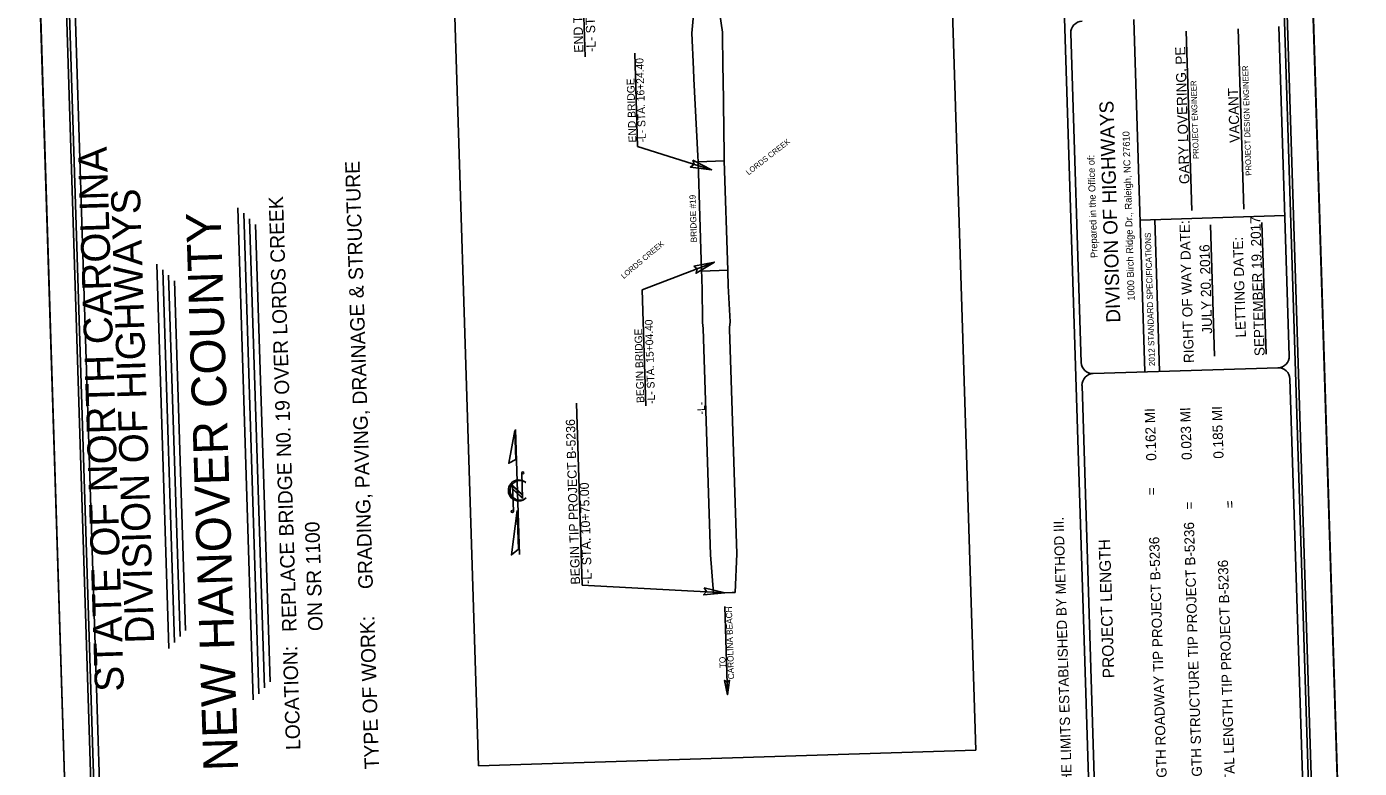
# Model space of a CAD drawing. Extents: x 2308163 to 2335412, y -96774 to 125428.
# Drawn here: x 2325774 to 2327503, y 123508 to 124471 of the extents above; entities that cross this region are included whole.
import ezdxf

# ---------------------------------------------------------------- set-up
doc = ezdxf.new("R2010")
doc.units = 0
for name, color, linetype in [('Prop Horizontal Alignment', 7, 'Continuous'), ('Prop Horizontal Alignment Station Label', 7, 'Continuous'), ('Prop Shade Light', 7, 'Continuous'), ('Prop Shade Medium', 7, 'Continuous'), ('Prop Terminator CELL', 7, 'Continuous'), ('Sheet Cutting Line CELL', 7, 'Continuous'), ('Sheet Data Text CELL', 7, 'Continuous'), ('Sheet North Arrow CELL', 7, 'Continuous'), ('Sheet Plan Layout CELL', 7, 'Continuous'), ('Sheet Plot Border Inside CELL', 7, 'Continuous'), ('Sheet Plot Border Outside CELL', 7, 'Continuous'), ('Sheet Title CELL', 7, 'Continuous'), ('Sheet Title Data Points CELL', 7, 'Continuous'), ('Typical Terminator CELL', 7, 'Continuous')]:
    doc.layers.add(name, color=color, linetype=linetype)

# ---------------------------------------------------------------- blocks, each defined once
blk = doc.blocks.new('NORTH ARROW')
at = {"layer": 'Sheet North Arrow CELL'}
for p, q in [((0, -3.25), (0, 3.25)), ((0.245, 0.988), (0.245, -0.346)), ((0.245, -0.138), (-0.252, 0.359)), ((-0.252, 0.359), (-0.252, -0.997)), ((0.245, -0.187), (-0.252, 0.31)), ((-0.252, 0.31), (-0.252, 0.188)), ((0.245, -0.309), (-0.252, 0.188)), ((-0.252, 0.188), (0.245, -0.309)), ((0.245, -0.346), (-0.252, 0.151)), ((0.429, 0.491), (0.436, 0.486)), ((0.245, -0.309), (0.245, -0.187))]:
    blk.add_line(p, q, dxfattribs=at)
for points in [[(-0.045, 3.193), (-0.416, 1.505), (-0.045, 1.693)], [(-0.053, -0.96), (-0.421, -3.25), (-0.053, -2.96)]]:
    blk.add_lwpolyline(points, close=True, dxfattribs=at)
for centre in [(0.298, 0.987), (-0.305, -0.999)]:
    blk.add_circle(centre, 0.053, dxfattribs=at)
for centre, radius, start, end in [((0.069, 0.081), 0.546, 47.84002, 312.39406), ((0.122, 0.082), 0.512, 53.09504, 308.62871)]:
    blk.add_arc(centre, radius, start, end, dxfattribs=at)
blk = doc.blocks.new('TERMINATOR')
at = {"layer": 'Typical Terminator CELL'}
blk.add_lwpolyline([(-0.469, 0.081), (0, 0), (-0.471, -0.083), (-0.411, 0)], close=True, dxfattribs=at)

msp = doc.modelspace()

# ---------------------------------------------------------------- linework, layer by layer
at = {"layer": 'Prop Horizontal Alignment'}
for p, q in [((2326491.4, 124659.7), (2326498.6, 124431.4)), ((2326562.8, 124436.4), (2326566.6, 124315)), ((2326566.6, 124315), (2326662.4, 124284.9)), ((2326666.1, 124165), (2326572.5, 124128.9)), ((2326572.5, 124128.9), (2326577.2, 123978.7)), ((2326487.3, 123982.1), (2326494.8, 123745.6)), ((2326679.6, 123735.8), (2326494.8, 123745.6)), ((2326683.3, 123603.4), (2326679.7, 123718))]:
    msp.add_line(p, q, dxfattribs=at)
at = {"layer": 'Prop Shade Light'}
for p, q in [((2326677.6, 124404.2), (2326677.2, 124416.7)), ((2326639.6, 124403), (2326644.8, 124303.1)), ((2326678.8, 124304.2), (2326677.6, 124404.2)), ((2326677.6, 124404.2), (2326677.6, 124404.2)), ((2326644.8, 124303.1), (2326644.8, 124303.1)), ((2326644.8, 124303.1), (2326644.8, 124303.1)), ((2326644.8, 124303.1), (2326645, 124295.4)), ((2326645, 124295.4), (2326679, 124296.4)), ((2326679, 124296.4), (2326678.8, 124304.2)), ((2326683.5, 124154.5), (2326649.5, 124153.4)), ((2326649.5, 124153.4), (2326649.7, 124145.7)), ((2326649.7, 124145.7), (2326649.9, 124139.5)), ((2326649.9, 124139.5), (2326649.9, 124139.5)), ((2326683.7, 124146.8), (2326683.5, 124154.5)), ((2326683.9, 124140.5), (2326683.7, 124146.8)), ((2326651.8, 124079), (2326661.1, 123785.2)), ((2326685.9, 124077.8), (2326685.8, 124080.1)), ((2326695.1, 123786.3), (2326685.9, 124077.8)), ((2326661.1, 123785.2), (2326665.2, 123735.3)), ((2326693.3, 123736.2), (2326695.1, 123786.3)), ((2326665.2, 123735.3), (2326669.8, 123735.5)), ((2326669.8, 123735.5), (2326689.4, 123736.1)), ((2326689.4, 123736.1), (2326693.3, 123736.2))]:
    msp.add_line(p, q, dxfattribs=at)
for points in [[(2326633.5, 124659.8), (2326639, 124485.8), (2326636.8, 124462.2), (2326639.2, 124415.5), (2326639.6, 124403)], [(2326677.2, 124416.7), (2326676.7, 124463.4), (2326673, 124486.8), (2326667.5, 124660.9)], [(2326649.9, 124139.5), (2326650.1, 124133.2), (2326650.7, 124086.5), (2326651.8, 124079)], [(2326685.8, 124080.1), (2326686.5, 124087.6), (2326684.1, 124134.3), (2326683.9, 124140.5)]]:
    msp.add_lwpolyline(points, dxfattribs=at)
at = {"layer": 'Prop Shade Medium'}
msp.add_lwpolyline([(2326683.5, 124154.5), (2326679, 124296.4), (2326645, 124295.4), (2326649.5, 124153.4), (2326683.5, 124154.5)], dxfattribs=at)
at = {"layer": 'Prop Terminator CELL'}
for points in [[(2326638, 124297.4), (2326662.4, 124284.9), (2326635, 124288.5), (2326639.7, 124292)], [(2326639.3, 124159.6), (2326666.1, 124165), (2326642.5, 124150.7), (2326644, 124156.5)], [(2326653, 123742.4), (2326679.6, 123735.9), (2326652.2, 123733), (2326656, 123737.5)]]:
    msp.add_lwpolyline(points, close=True, dxfattribs=at)
at = {"layer": 'Sheet Cutting Line CELL'}
for p, q in [((2327502.8, 122587.5), (2327423.2, 125112.3)), ((2325853.6, 122535.6), (2325774, 125060.3))]:
    msp.add_line(p, q, dxfattribs=at)
at = {"layer": 'Sheet Plan Layout CELL'}
msp.add_lwpolyline([(2326360.1, 123511.4), (2326318.3, 124840), (2326963.2, 124860.3), (2327005.1, 123531.7)], close=True, dxfattribs=at)
at = {"layer": 'Sheet Plot Border Inside CELL'}
msp.add_lwpolyline([(2327468.5, 122606), (2327389.8, 125104.5), (2325807.9, 125054.6), (2325886.6, 122556.1)], close=True, dxfattribs=at)
at = {"layer": 'Sheet Plot Border Outside CELL'}
msp.add_lwpolyline([(2325774, 125060.3), (2325853.6, 122535.6), (2327502.8, 122587.5), (2327423.2, 125112.3)], close=True, dxfattribs=at)
at = {"layer": 'Sheet Title CELL'}
for p, q in [((2327169.5, 122925.2), (2327102.4, 125054.2)), ((2327210.2, 124479.8), (2327224.6, 124022.5)), ((2327353, 124233.8), (2327345.6, 124468)), ((2327142, 124034.9), (2327128.5, 124462.2)), ((2327285.5, 124232.2), (2327278.2, 124464.8)), ((2326068, 123597), (2326047.9, 124235.7)), ((2326075.2, 123604.7), (2326055.6, 124228.4)), ((2326082.5, 123612.4), (2326063.3, 124221.1)), ((2326089.8, 123620.2), (2326071.1, 124213.9)), ((2327218.3, 124219.7), (2327406.1, 124225.6)), ((2327237.5, 124220.3), (2327243.7, 124023.1)), ((2327309.5, 124213.6), (2327314.8, 124043)), ((2327376.3, 124216.3), (2327381.7, 124045.7)), ((2325958.4, 123663.5), (2325942.7, 124162.4)), ((2327239.2, 124163.5), (2327239.2, 124163.5)), ((2325965.7, 123671.3), (2325950.5, 124155.2)), ((2325973, 123679), (2325958.2, 124147.9)), ((2325980.2, 123686.7), (2325965.9, 124140.6)), ((2327312.2, 124128.3), (2327312.2, 124128.3)), ((2327157.5, 124020.4), (2327397.3, 124027.9)), ((2327160.9, 123435.2), (2327143, 124004.9))]:
    msp.add_line(p, q, dxfattribs=at)
for points in [[(2327456.9, 122851.7), (2327387, 125070.6)], [(2325812.8, 125021), (2325882.7, 122802.1)], [(2325820.5, 125013.8), (2325887.6, 122884.8)], [(2327411.9, 124043.4), (2327398.4, 124470.7)], [(2327430.8, 123443.7), (2327412.8, 124013.4)]]:
    msp.add_lwpolyline(points, dxfattribs=at)
for centre, start, end in [((2327143.5, 124462.7), 91.8048, 181.8048), ((2327396.8, 124042.9), 271.8048, 1.8048), ((2327156.9, 124035.4), 181.8048, 271.8048), ((2327157.9, 124005.4), 91.8048, 181.8048), ((2327397.7, 124012.9), 1.8048, 91.8048)]:
    msp.add_arc(centre, 15, start, end, dxfattribs=at)
at = {"layer": 'Sheet Title Data Points CELL'}
for p, q in [((2326113.9, 124018.4), (2326113.9, 124018.4)), ((2326035.5, 123917.9), (2326035.5, 123917.9))]:
    msp.add_line(p, q, dxfattribs=at)

# ---------------------------------------------------------------- block references
at = {"layer": 'Prop Horizontal Alignment', "xscale": 40, "yscale": 40.00000000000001, "rotation": -88.19520799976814}
msp.add_blockref('TERMINATOR', (2326683.3, 123603.4), dxfattribs=at)
at = {"layer": 'Sheet Plan Layout CELL', "xscale": 25.000000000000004, "yscale": 25, "rotation": 1.8047920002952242}
msp.add_blockref('NORTH ARROW', (2326410.9, 123866.6), dxfattribs=at)

# ---------------------------------------------------------------- texts
at = {"layer": 'Prop Horizontal Alignment'}
for s, height, rotation, p in [('END TIP PROJECT B-5236', 12, 91.8048, (2326496.4, 124437)), ('-L- STA. 20+50.00', 12, 91.8048, (2326512.4, 124438.1)), ('-L- STA. 16+24.40', 10, 91.8048, (2326577.4, 124320.5)), ('END BRIDGE', 10, 91.8048, (2326564.9, 124320.5)), ('LORDS CREEK', 7, 38.0911, (2326710.5, 124277.5)), ('BRIDGE #19', 8, 91.8048, (2326643.6, 124190.8)), ('LORDS CREEK', 7, 40.2703, (2326548.6, 124142.9)), ('-L- STA. 15+04.40', 10, 91.8048, (2326589.3, 123981.1)), ('BEGIN BRIDGE', 10, 91.8048, (2326575.3, 123982.4)), ('-L-', 10, 91.8048, (2326654.1, 123967.5)), ('-L- STA. 10+75.00', 12, 91.8048, (2326507.3, 123747.7)), ('CAROLINA BEACH', 8, 91.8048, (2326691.8, 123623.7)), ('     TO', 8, 91.8048, (2326681.4, 123623.3))]:
    msp.add_text(s, height=height, rotation=rotation, dxfattribs=at).set_placement(p)
at = {"layer": 'Prop Horizontal Alignment Station Label'}
msp.add_text('BEGIN TIP PROJECT B-5236', height=12, rotation=91.8048, dxfattribs=at).set_placement((2326492, 123746.7))
at = {"layer": 'Sheet Data Text CELL'}
for s, height, rotation, p in [('GARY LOVERING, PE', 13.125, 91.8048, (2327282.5, 124266.6)), ('VACANT', 13.13, 91.8048, (2327347.6, 124320.1)), ('GRADING, PAVING, DRAINAGE & STRUCTURE', 18.75, 91.8048, (2326223.3, 123741)), ('REPLACE BRIDGE N0. 19 OVER LORDS CREEK', 18.75, 91.8048, (2326124.4, 123685.4)), ('NEW HANOVER COUNTY', 45, 91.8048, (2326048.5, 123505.2)), ('SEPTEMBER 19, 2017', 13.125, 91.8048, (2327380, 124043.3)), ('JULY 20, 2016', 13.125, 91.8048, (2327312, 124072.2)), ('0.162 MI', 13.13, 91.8048, (2327239.5, 123907.4)), ('0.023 MI', 13.13, 91.8048, (2327285.5, 123908.5)), ('0.185 MI', 13.13, 91.8048, (2327326.7, 123910.1)), (' =', 13.13, 91.8048, (2327240, 123857.8)), (' =', 13.13, 271.8048, (2327275.6, 123858.9)), (' =', 13.13, 271.8048, (2327328.2, 123860.5)), ('CLEARING ON THIS PROJECT SHALL BE PERFORMED TO THE LIMITS ESTABLISHED BY METHOD III.', 13.125, 91.8048, (2327145.7, 122986.4)), ('ON SR 1100', 18.75, 91.8048, (2326158.1, 123686.5)), ('LENGTH STRUCTURE TIP PROJECT B-5236', 13.125, 91.8048, (2327299.7, 123463.3)), ('LENGTH ROADWAY TIP PROJECT B-5236', 13.125, 91.8048, (2327254, 123461.8)), ('TOTAL LENGTH TIP PROJECT B-5236', 13.125, 91.8048, (2327342.1, 123465.9))]:
    msp.add_text(s, height=height, rotation=rotation, dxfattribs=at).set_placement(p)
at = {"layer": 'Sheet Title CELL'}
for s, height, p in [('PROJECT DESIGN ENGINEER', 7.499, (2327362.9, 124277.2)), ('PROJECT ENGINEER', 7.499, (2327294.6, 124299)), ('DIVISION OF HIGHWAYS', 18.281, (2327192.8, 124086.8)), ('1000 Birch Ridge Dr., Raleigh, NC 27610', 9, (2327211.4, 124115.1)), ('STATE OF NORTH CAROLINA', 37.5, (2325900.2, 123608)), ('Prepared in the Office of:', 8.999, (2327163.2, 124170.6)), ('DIVISION OF HIGHWAYS', 37.5, (2325939.5, 123670.6)), ('RIGHT OF WAY DATE: ', 13.125, (2327288.3, 124034.3)), ('2012 STANDARD SPECIFICATIONS', 7.8, (2327237.7, 124030.2)), ('LETTING DATE:', 13.125, (2327355.7, 124067.4)), ('PROJECT LENGTH', 14.999, (2327185.1, 123625.2)), ('TYPE OF WORK:', 18.75, (2326231.3, 123507.1)), ('LOCATION: ', 18.75, (2326129.2, 123532.1))]:
    msp.add_text(s, height=height, rotation=91.8048, dxfattribs=at).set_placement(p)

doc.saveas('drawing.dxf')
